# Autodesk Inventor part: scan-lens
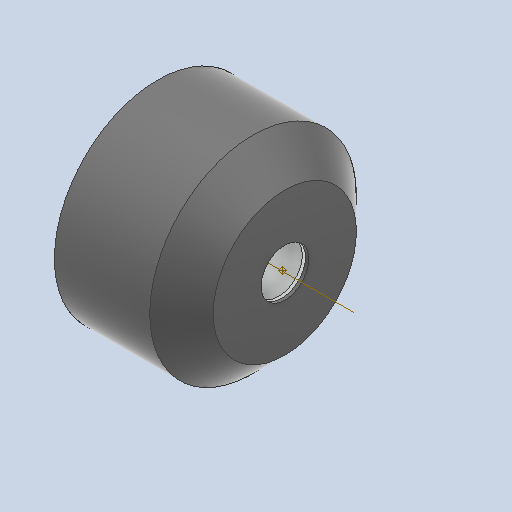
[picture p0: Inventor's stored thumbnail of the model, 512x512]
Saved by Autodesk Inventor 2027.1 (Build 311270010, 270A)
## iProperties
Created: 2026-07
Part Number: scan-lens
Material: Generic
Document SubType Name: Modeling
Designer: dunge
Density: 1 g/cm^3
Appearance: Default
Author: dunge
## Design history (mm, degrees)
sketch "Sketch1"
  geometry: L1 (0, 0)-(1.016, 0); L2 (15.24, 16.51)-(0, 16.51); L3 (0, 16.51)-(0, 0); L4 (15.24, 16.51)-(20.32, 11.43); L5 (20.32, 11.43)-(20.32, 3.81); L6 (20.32, 3.81)-(19.812, 3.81); L7 (19.812, 3.81)-(19.812, 0); L8 (19.812, 0)-(19.304, 0); L9 (0.508, 3.81)-(0.508, 0); L10 (0.508, 3.81)-(0, 3.81); L11 (1.016, 0)-(1.016, 3.81); L12 (1.016, 3.81)-(19.304, 3.81); L13 (19.304, 3.81)-(19.304, 0); 1 further point
  constraints: 26 end point, 6 perpendicular, 3 point on line, 3 vertical, 2 coincident, 2 horizontal, 2 parallel, 1 midpoint
  dimensions: "d0" = 16.51 distance of L2.end L1.start; "d4" = 0.508 distance of L5.end L6.end; "d5" = 3.81 distance of L6.end L7.end; "d9" = 135 deg angle of L2 L4; "d10" = 0.508 distance of L9.start L10.end; "BODY_SIZE" = 20.32 distance between parallel lines of L3 L5; "d12" = 5.08 horizontal distance of L2.start L4.end; "d13" = 0.508 distance of L7.end L8.end; "d14" = 0.508 distance between parallel lines of L9 L11
revolve "Revolution1" sketch "Sketch1" stored, may be unused: angle "d6" = 360 deg
workpoint "Work Point1"
  workaxis "Work Axis1"
body "Solid1"
node "Finishes"
node "Finish1" dims "Finish1_Area" = 403.16221
node "Finish2" dims "Finish2_Area" = 18.24147
